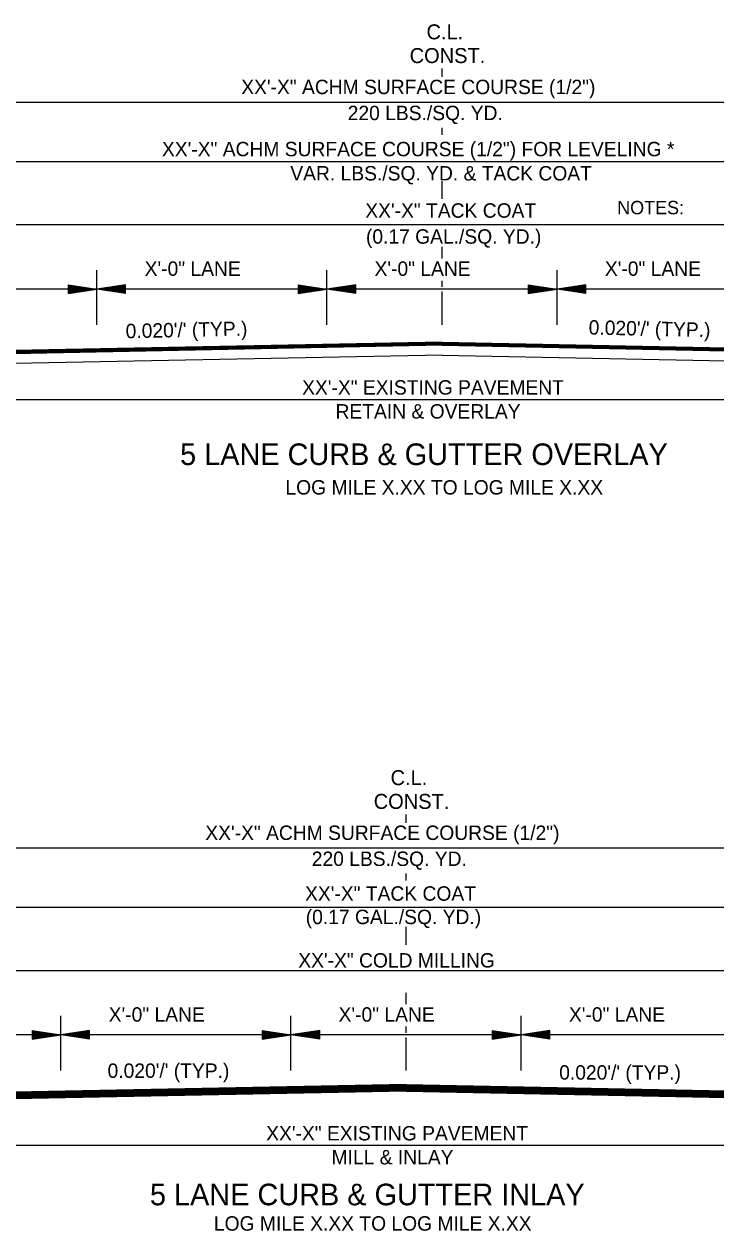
# Model space of a CAD drawing. Extents: x 544199 to 1930787, y -1968972 to 596640.
# Drawn here: x 551786 to 552147, y -1968972 to -1968343 of the extents above; entities that cross this region are included whole.
import ezdxf

# ---------------------------------------------------------------- set-up
doc = ezdxf.new("R2010")
doc.units = 0
doc.layers.add('R_Border Notes', color=7, linetype='Continuous')
doc.layers.add('R_Draft', color=7, linetype='Continuous')

msp = doc.modelspace()

# ---------------------------------------------------------------- linework, layer by layer
at = {"layer": 'R_Draft'}
for p, q in [((552003.92, -1968370.94), (552003.92, -1968366.52)), ((551696.09, -1968384.04), (552311.66, -1968384.04)), ((552003.92, -1968401.07), (552003.92, -1968397.39)), ((551696.09, -1968414.91), (552311.66, -1968414.91)), ((552003.92, -1968434.42), (552003.92, -1968425.12)), ((551696.09, -1968447.84), (552311.66, -1968447.84)), ((552003.92, -1968465.49), (552003.92, -1968459.49)), ((551824, -1968500.03), (551824, -1968471.48)), ((551943.92, -1968481.38), (551943.92, -1968471.48)), ((551943.92, -1968500.03), (551943.92, -1968471.48)), ((552063.92, -1968500.03), (552063.92, -1968471.48)), ((551809, -1968479.13), (551824, -1968481.38)), ((551809, -1968479.13), (551809, -1968483.63)), ((551809, -1968479.5), (551821.49, -1968481.38)), ((551809, -1968479.88), (551818.91, -1968481.38)), ((551809, -1968480.26), (551816.41, -1968481.38)), ((551839, -1968479.13), (551824, -1968481.38)), ((551839, -1968479.5), (551826.5, -1968481.38)), ((551839, -1968479.88), (551829.08, -1968481.38)), ((551839, -1968480.26), (551831.58, -1968481.38)), ((551839, -1968483.63), (551839, -1968479.13)), ((551928.92, -1968479.13), (551943.92, -1968481.38)), ((551928.92, -1968479.13), (551928.92, -1968483.63)), ((551928.92, -1968479.5), (551941.42, -1968481.38)), ((551928.92, -1968479.88), (551938.84, -1968481.38)), ((551928.92, -1968480.26), (551936.34, -1968481.38)), ((551958.92, -1968479.13), (551943.92, -1968481.38)), ((551958.92, -1968479.5), (551946.43, -1968481.38)), ((551958.92, -1968479.88), (551949.01, -1968481.38)), ((551958.92, -1968480.26), (551951.51, -1968481.38)), ((551958.92, -1968483.63), (551958.92, -1968479.13)), ((552003.92, -1968480.27), (552003.92, -1968477.12)), ((552048.85, -1968479.13), (552063.85, -1968481.38)), ((552048.85, -1968479.13), (552048.85, -1968483.63)), ((552048.85, -1968479.5), (552061.34, -1968481.38)), ((552048.85, -1968479.88), (552058.76, -1968481.38)), ((552048.85, -1968480.26), (552056.27, -1968481.38)), ((552078.85, -1968479.13), (552063.85, -1968481.38)), ((552078.85, -1968479.5), (552066.35, -1968481.38)), ((552078.85, -1968479.88), (552068.93, -1968481.38)), ((552078.85, -1968480.26), (552071.43, -1968481.38)), ((552078.85, -1968483.63), (552078.85, -1968479.13)), ((551824, -1968481.38), (551704, -1968481.38)), ((551809, -1968480.65), (551813.87, -1968481.38)), ((551809, -1968481.02), (551811.37, -1968481.38)), ((551809, -1968483.63), (551824, -1968481.38)), ((551809, -1968482.11), (551813.87, -1968481.38)), ((551809, -1968482.87), (551818.91, -1968481.38)), ((551809, -1968483.25), (551821.49, -1968481.38)), ((551809, -1968482.49), (551816.41, -1968481.38)), ((551809, -1968481.73), (551811.37, -1968481.38)), ((551943.92, -1968481.38), (551824, -1968481.38)), ((551839, -1968483.63), (551824, -1968481.38)), ((551839, -1968483.25), (551826.5, -1968481.38)), ((551839, -1968482.87), (551829.08, -1968481.38)), ((551839, -1968482.49), (551831.58, -1968481.38)), ((551839, -1968480.64), (551834.12, -1968481.38)), ((551839, -1968482.1), (551834.12, -1968481.38)), ((551839, -1968481.02), (551836.63, -1968481.38)), ((551839, -1968481.73), (551836.63, -1968481.38)), ((551928.92, -1968480.65), (551933.8, -1968481.38)), ((551928.92, -1968481.02), (551931.29, -1968481.38)), ((551928.92, -1968483.63), (551943.92, -1968481.38)), ((551928.92, -1968482.11), (551933.8, -1968481.38)), ((551928.92, -1968482.87), (551938.84, -1968481.38)), ((551928.92, -1968483.25), (551941.42, -1968481.38)), ((551928.92, -1968482.49), (551936.34, -1968481.38)), ((551928.92, -1968481.73), (551931.29, -1968481.38)), ((551943.92, -1968500.03), (551943.92, -1968481.38)), ((552063.85, -1968481.38), (551943.92, -1968481.38)), ((551958.92, -1968483.63), (551943.92, -1968481.38)), ((551958.92, -1968483.25), (551946.43, -1968481.38)), ((551958.92, -1968482.87), (551949.01, -1968481.38)), ((551958.92, -1968482.49), (551951.51, -1968481.38)), ((551958.92, -1968480.64), (551954.05, -1968481.38)), ((551958.92, -1968482.1), (551954.05, -1968481.38)), ((551958.92, -1968481.02), (551956.55, -1968481.38)), ((551958.92, -1968481.73), (551956.55, -1968481.38)), ((552003.92, -1968500.03), (552003.92, -1968482.75)), ((552048.85, -1968480.65), (552053.72, -1968481.38)), ((552048.85, -1968481.02), (552051.22, -1968481.38)), ((552048.85, -1968483.63), (552063.85, -1968481.38)), ((552048.85, -1968482.11), (552053.72, -1968481.38)), ((552048.85, -1968482.87), (552058.76, -1968481.38)), ((552048.85, -1968483.25), (552061.34, -1968481.38)), ((552048.85, -1968482.49), (552056.27, -1968481.38)), ((552048.85, -1968481.73), (552051.22, -1968481.38)), ((552183.78, -1968481.38), (552063.85, -1968481.38)), ((552078.85, -1968483.63), (552063.85, -1968481.38)), ((552078.85, -1968483.25), (552066.35, -1968481.38)), ((552078.85, -1968482.87), (552068.93, -1968481.38)), ((552078.85, -1968482.49), (552071.43, -1968481.38)), ((552078.85, -1968480.64), (552073.97, -1968481.38)), ((552078.85, -1968482.1), (552073.97, -1968481.38)), ((552078.85, -1968481.02), (552076.48, -1968481.38)), ((552078.85, -1968481.73), (552076.48, -1968481.38)), ((552003.92, -1968508.99), (551696.09, -1968515.15)), ((552003.92, -1968509.29), (551696.28, -1968515.44)), ((552003.92, -1968509.59), (551696.47, -1968515.74)), ((552003.92, -1968509.89), (551696.66, -1968516.03)), ((552003.92, -1968510.19), (551696.84, -1968516.33)), ((552003.92, -1968510.49), (551697.03, -1968516.63)), ((552003.92, -1968510.69), (551704, -1968516.69)), ((552003.92, -1968508.99), (552311.66, -1968515.14)), ((552003.92, -1968509.29), (552311.48, -1968515.44)), ((552003.92, -1968509.59), (552311.29, -1968515.74)), ((552003.92, -1968509.89), (552311.1, -1968516.03)), ((552003.92, -1968510.19), (552310.91, -1968516.33)), ((552003.92, -1968510.49), (552310.73, -1968516.63)), ((552003.92, -1968510.69), (552303.68, -1968516.68)), ((552003.99, -1968515.79), (551704, -1968521.79)), ((552003.99, -1968515.79), (552303.68, -1968521.78)), ((551704, -1968538.84), (552303.68, -1968538.84)), ((551985.19, -1968759.42), (551985.19, -1968755)), ((551685.27, -1968772.52), (552284.97, -1968772.52)), ((551985.19, -1968789.54), (551985.19, -1968785.87)), ((551685.27, -1968803.39), (552284.97, -1968803.39)), ((551985.19, -1968822.9), (551985.19, -1968813.6)), ((551685.27, -1968836.32), (552284.97, -1968836.32)), ((551985.19, -1968853.96), (551985.19, -1968847.97)), ((551805.27, -1968888.51), (551805.27, -1968859.96)), ((551925.19, -1968869.85), (551925.19, -1968859.96)), ((551925.19, -1968888.51), (551925.19, -1968859.96)), ((552045.19, -1968888.51), (552045.19, -1968859.96)), ((551805.27, -1968869.85), (551685.27, -1968869.85)), ((551790.27, -1968867.6), (551805.27, -1968869.85)), ((551790.27, -1968867.6), (551790.27, -1968872.1)), ((551790.27, -1968867.98), (551802.76, -1968869.85)), ((551790.27, -1968868.36), (551800.18, -1968869.85)), ((551790.27, -1968868.74), (551797.68, -1968869.85)), ((551790.27, -1968869.13), (551795.14, -1968869.85)), ((551790.27, -1968869.5), (551792.64, -1968869.85)), ((551790.27, -1968872.1), (551805.27, -1968869.85)), ((551790.27, -1968870.59), (551795.14, -1968869.85)), ((551790.27, -1968871.35), (551800.18, -1968869.85)), ((551790.27, -1968871.73), (551802.76, -1968869.85)), ((551790.27, -1968870.97), (551797.68, -1968869.85)), ((551790.27, -1968870.21), (551792.64, -1968869.85)), ((551820.27, -1968867.6), (551805.27, -1968869.85)), ((551925.19, -1968869.85), (551805.27, -1968869.85)), ((551820.27, -1968872.1), (551805.27, -1968869.85)), ((551820.27, -1968867.98), (551807.77, -1968869.85)), ((551820.27, -1968871.73), (551807.77, -1968869.85)), ((551820.27, -1968868.36), (551810.35, -1968869.85)), ((551820.27, -1968871.35), (551810.35, -1968869.85)), ((551820.27, -1968868.74), (551812.85, -1968869.85)), ((551820.27, -1968870.97), (551812.85, -1968869.85)), ((551820.27, -1968869.12), (551815.39, -1968869.85)), ((551820.27, -1968870.58), (551815.39, -1968869.85)), ((551820.27, -1968869.5), (551817.9, -1968869.85)), ((551820.27, -1968870.21), (551817.9, -1968869.85)), ((551820.27, -1968872.1), (551820.27, -1968867.6)), ((551910.19, -1968867.6), (551925.19, -1968869.85)), ((551910.19, -1968867.6), (551910.19, -1968872.1)), ((551910.19, -1968867.98), (551922.69, -1968869.85)), ((551910.19, -1968868.36), (551920.11, -1968869.85)), ((551910.19, -1968868.74), (551917.61, -1968869.85)), ((551910.19, -1968869.13), (551915.07, -1968869.85)), ((551910.19, -1968869.5), (551912.56, -1968869.85)), ((551910.19, -1968872.1), (551925.19, -1968869.85)), ((551910.19, -1968870.59), (551915.07, -1968869.85)), ((551910.19, -1968871.35), (551920.11, -1968869.85)), ((551910.19, -1968871.73), (551922.69, -1968869.85)), ((551910.19, -1968870.97), (551917.61, -1968869.85)), ((551910.19, -1968870.21), (551912.56, -1968869.85)), ((551940.19, -1968867.6), (551925.19, -1968869.85)), ((551925.19, -1968888.51), (551925.19, -1968869.85)), ((552045.12, -1968869.85), (551925.19, -1968869.85)), ((551940.19, -1968872.1), (551925.19, -1968869.85)), ((551940.19, -1968867.98), (551927.7, -1968869.85)), ((551940.19, -1968871.73), (551927.7, -1968869.85)), ((551940.19, -1968868.36), (551930.28, -1968869.85)), ((551940.19, -1968871.35), (551930.28, -1968869.85)), ((551940.19, -1968868.74), (551932.78, -1968869.85)), ((551940.19, -1968870.97), (551932.78, -1968869.85)), ((551940.19, -1968869.12), (551935.32, -1968869.85)), ((551940.19, -1968870.58), (551935.32, -1968869.85)), ((551940.19, -1968869.5), (551937.82, -1968869.85)), ((551940.19, -1968870.21), (551937.82, -1968869.85)), ((551940.19, -1968872.1), (551940.19, -1968867.6)), ((551985.19, -1968868.75), (551985.19, -1968865.59)), ((552030.12, -1968867.6), (552045.12, -1968869.85)), ((552030.12, -1968867.6), (552030.12, -1968872.1)), ((552030.12, -1968867.98), (552042.62, -1968869.85)), ((552030.12, -1968868.36), (552040.04, -1968869.85)), ((552030.12, -1968868.74), (552037.54, -1968869.85)), ((552030.12, -1968869.13), (552035, -1968869.85)), ((552030.12, -1968869.5), (552032.49, -1968869.85)), ((552030.12, -1968872.1), (552045.12, -1968869.85)), ((552030.12, -1968870.59), (552035, -1968869.85)), ((552030.12, -1968871.35), (552040.04, -1968869.85)), ((552030.12, -1968871.73), (552042.62, -1968869.85)), ((552030.12, -1968870.97), (552037.54, -1968869.85)), ((552030.12, -1968870.21), (552032.49, -1968869.85)), ((552060.12, -1968867.6), (552045.12, -1968869.85)), ((552165.05, -1968869.85), (552045.12, -1968869.85)), ((552060.12, -1968872.1), (552045.12, -1968869.85)), ((552060.12, -1968867.98), (552047.63, -1968869.85)), ((552060.12, -1968871.73), (552047.63, -1968869.85)), ((552060.12, -1968868.36), (552050.21, -1968869.85)), ((552060.12, -1968871.35), (552050.21, -1968869.85)), ((552060.12, -1968868.74), (552052.7, -1968869.85)), ((552060.12, -1968870.97), (552052.7, -1968869.85)), ((552060.12, -1968869.12), (552055.25, -1968869.85)), ((552060.12, -1968870.58), (552055.25, -1968869.85)), ((552060.12, -1968869.5), (552057.75, -1968869.85)), ((552060.12, -1968870.21), (552057.75, -1968869.85)), ((552060.12, -1968872.1), (552060.12, -1968867.6)), ((551985.19, -1968888.51), (551985.19, -1968871.23)), ((551985.19, -1968895.67), (551685.27, -1968901.66)), ((551985.19, -1968895.97), (551685.27, -1968901.96)), ((551985.19, -1968896.27), (551685.27, -1968902.26)), ((551985.19, -1968896.57), (551685.27, -1968902.56)), ((551985.19, -1968896.87), (551685.27, -1968902.86)), ((551985.19, -1968897.17), (551685.27, -1968903.16)), ((551985.19, -1968897.47), (551685.27, -1968903.46)), ((551985.19, -1968897.77), (551685.27, -1968903.76)), ((551985.19, -1968898.07), (551685.27, -1968904.06)), ((551985.19, -1968898.37), (551685.27, -1968904.37)), ((551985.19, -1968898.67), (551685.27, -1968904.67)), ((551985.19, -1968898.97), (551685.27, -1968904.97)), ((551985.19, -1968899.16), (551685.27, -1968905.16)), ((551985.19, -1968895.67), (552284.95, -1968901.66)), ((551985.19, -1968895.97), (552284.95, -1968901.96)), ((551985.19, -1968896.27), (552284.95, -1968902.26)), ((551985.19, -1968896.57), (552284.95, -1968902.56)), ((551985.19, -1968896.87), (552284.95, -1968902.86)), ((551985.19, -1968897.17), (552284.95, -1968903.16)), ((551985.19, -1968897.47), (552284.95, -1968903.46)), ((551985.19, -1968897.77), (552284.95, -1968903.76)), ((551985.19, -1968898.07), (552284.95, -1968904.06)), ((551985.19, -1968898.37), (552284.95, -1968904.36)), ((551985.19, -1968898.67), (552284.95, -1968904.66)), ((551985.19, -1968898.97), (552284.95, -1968904.96)), ((551985.19, -1968899.16), (552284.95, -1968905.15)), ((551685.27, -1968927.32), (552284.95, -1968927.32))]:
    msp.add_line(p, q, dxfattribs=at)

# ---------------------------------------------------------------- texts
at = {"layer": 'R_Border Notes'}
msp.add_text('NOTES: ', height=7, dxfattribs=at).set_placement((552095.18, -1968442.46))
at = {"layer": 'R_Draft'}
for s, height, p in [('C.L.', 7.8, (551995.82, -1968351.32)), ('CONST.', 7.8, (551987.04, -1968363.69)), ('XX\'-X" ACHM SURFACE COURSE (1/2")', 7.5, (551899.27, -1968379.87)), ('220 LBS./SQ. YD. ', 7.5, (551954.75, -1968393.42)), ('XX\'-X" ACHM SURFACE COURSE (1/2") FOR LEVELING *', 7.5, (551857.95, -1968412.23)), ('VAR. LBS./SQ. YD. & TACK COAT', 7.5, (551924.84, -1968424.84)), ('XX\'-X" TACK COAT', 7.5, (551963.91, -1968444.23)), ('(0.17 GAL./SQ. YD.)', 7.5, (551964.26, -1968457.77)), ('X\'-0" LANE', 7.5, (551848.93, -1968474.51)), ('X\'-0" LANE', 7.5, (551968.73, -1968474.51)), ('X\'-0" LANE', 7.5, (552088.78, -1968474.51)), ('XX\'-X" EXISTING PAVEMENT', 7.5, (551931, -1968536.38)), ('RETAIN & OVERLAY', 7.5, (551948.41, -1968548.85)), ('5 LANE CURB & GUTTER OVERLAY', 11.25, (551867.4, -1968573.06)), ('LOG MILE X.XX TO LOG MILE X.XX', 7.5, (551922.31, -1968588.42)), ('C.L.', 7.8, (551977.09, -1968739.8)), ('CONST.', 7.8, (551968.31, -1968752.17)), ('XX\'-X" ACHM SURFACE COURSE (1/2")', 7.5, (551880.54, -1968768.35)), ('220 LBS./SQ. YD. ', 7.5, (551936.02, -1968781.89)), ('XX\'-X" TACK COAT', 7.5, (551932.53, -1968799.99)), ('(0.17 GAL./SQ. YD.)', 7.5, (551932.89, -1968812.18)), ('XX\'-X" COLD MILLING', 7.5, (551928.99, -1968834.8)), ('X\'-0" LANE', 7.5, (551830.2, -1968862.99)), ('X\'-0" LANE', 7.5, (551950, -1968862.99)), ('X\'-0" LANE', 7.5, (552070.05, -1968862.99)), ("0.020'/' (TYP.)", 7.5, (551829.61, -1968892.26)), ("0.020'/' (TYP.)", 7.5, (552064.96, -1968893.19)), ('XX\'-X" EXISTING PAVEMENT', 7.5, (551912.27, -1968924.86)), ('MILL & INLAY', 7.5, (551946.33, -1968937.33)), ('5 LANE CURB & GUTTER INLAY', 11.25, (551851.69, -1968958.63)), ('LOG MILE X.XX TO LOG MILE X.XX', 7.5, (551885.03, -1968971.85))]:
    msp.add_text(s, height=height, dxfattribs=at).set_placement(p)
for rotation, p in [(1.26463, (551839.1, -1968507.06)), (358.74062, (552080.26, -1968505.06))]:
    msp.add_text("0.020'/' (TYP.)", height=7.5, rotation=rotation, dxfattribs=at).set_placement(p)

doc.saveas('drawing.dxf')
